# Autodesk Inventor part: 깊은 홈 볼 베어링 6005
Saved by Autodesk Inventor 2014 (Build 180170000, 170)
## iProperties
Created: 2026-04
Part Number: 깊은 홈 볼 베어링 6005
Material: 일반
Document SubType Name: Modeling
Designer: dg
Density: 1 g/cm^3
Appearance: 기본값
Author: dg
Author: jhkim
Description: 깊은 그루브 볼 베어링
Creation Date: 2026-03-27
Sending System: Autodesk Inventor 2026
Preprocessor: ST-DEVELOPER v20.1
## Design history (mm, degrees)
node "깊은 홈 볼 베어링 60051"
body "Solid1"
node "Solid1_1"
node "Solid1_2"
node "Solid1_3"
node "Solid1_4"
node "Solid1_5"
node "Solid1_6"
node "Solid1_7"
node "Solid1_8"
node "Solid1_9"
node "Solid1_10"
node "Solid1_11"
node "기준1"
node "기준2"
node "기준3"
node "기준4"
node "기준5"
node "기준6"
node "기준7"
node "기준8"
node "기준9"
node "기준10"
node "기준11"
node "기준12"
